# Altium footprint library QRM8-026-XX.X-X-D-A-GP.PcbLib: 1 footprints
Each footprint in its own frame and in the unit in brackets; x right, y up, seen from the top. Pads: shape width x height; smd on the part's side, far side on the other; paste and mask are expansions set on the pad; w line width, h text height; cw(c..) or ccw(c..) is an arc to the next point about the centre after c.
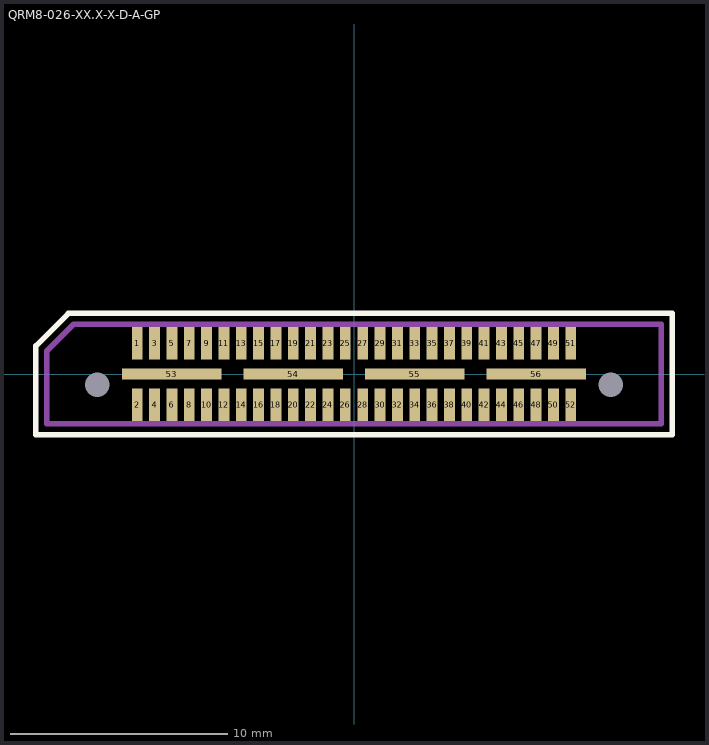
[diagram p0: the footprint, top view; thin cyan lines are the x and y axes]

## QRM8-026-XX.X-X-D-A-GP [mm]
pads (58):
  rect 0.5x1.5 smd mask+0.05: 1(-10,1.425) 2(-10,-1.425) 3(-9.2,1.425) 4(-9.2,-1.425) 5(-8.4,1.425) 6(-8.4,-1.425) 7(-7.6,1.425) 8(-7.6,-1.425) 9(-6.8,1.425) 10(-6.8,-1.425) 11(-6,1.425) 12(-6,-1.425) 13(-5.2,1.425) 14(-5.2,-1.425) 15(-4.4,1.425) 16(-4.4,-1.425) 17(-3.6,1.425) 18(-3.6,-1.425) 19(-2.8,1.425) 20(-2.8,-1.425) 21(-2,1.425) 22(-2,-1.425) 23(-1.2,1.425) 24(-1.2,-1.425) 25(-0.4,1.425) 26(-0.4,-1.425) 27(0.4,1.425) 28(0.4,-1.425) 29(1.2,1.425) 30(1.2,-1.425) 31(2,1.425) 32(2,-1.425) 33(2.8,1.425) 34(2.8,-1.425) 35(3.6,1.425) 36(3.6,-1.425) 37(4.4,1.425) 38(4.4,-1.425) 39(5.2,1.425) 40(5.2,-1.425) 41(6,1.425) 42(6,-1.425) 43(6.8,1.425) 44(6.8,-1.425) 45(7.6,1.425) 46(7.6,-1.425) 47(8.4,1.425) 48(8.4,-1.425) 49(9.2,1.425) 50(9.2,-1.425) 51(10,1.425) 52(10,-1.425)
  rect 4.6x0.51 smd mask+0.05: 53(-8.4,0) 54(-2.8,0) 55(2.8,0) 56(8.4,0)
  round 0 hole 1.13 unplated: 57(-11.85,-0.5) 58(11.85,-0.5)
Top Overlay:
  lines w0.254: -14.675,-2.8 14.675,-2.8 14.675,2.8 -13.175,2.8 -14.675,1.3 -14.675,-2.8
Mechanical 1:
  lines w0.254: -14.175,-2.3 14.175,-2.3 14.175,2.3 -12.925,2.3 -14.175,1.05 -14.175,-2.3
  text "J1" at -0.446,-0.457 h0.76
